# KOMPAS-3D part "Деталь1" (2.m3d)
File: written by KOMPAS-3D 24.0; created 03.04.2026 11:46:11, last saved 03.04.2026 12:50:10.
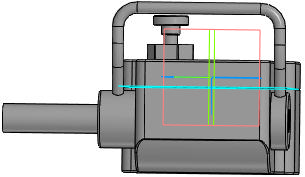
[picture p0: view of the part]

Document properties: Автор: R2D2; Полное имя файла: E:\Работа\Зайцев\Аксессуары для пневмоприводов\Ручной дублер DN.ru\MON1-250-T26-ISO Ручной дублер DN.ru\исходные материалы\2.m3d

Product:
- Body: Тело 2  | qty 1
    Масса: 4.429213
- Part/product: Деталь1
    Масса: 5.630796
    additional columns: Типовые

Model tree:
1. Операция без истории:1
2. Элемент выдавливания:1  (with: Грань.Операция без истории:1)
     Расстояние 1 = 0.5
3. Эскиз:1  (with: Ребро.Операция без истории:1)
4. Элемент выдавливания:2
     Расстояние 1 = 105; Расстояние 2 = 45
5. Эскиз:2  (with: Грань.Операция без истории:1)
6. Элемент выдавливания:3  (with: Грань.Операция без истории:1)
     Расстояние 2 = 19
7. Эскиз:3  (with: Ребро.Операция без истории:1)
8. Элемент выдавливания:4
     Расстояние 1 = 500
9. Смещенная плоскость:1  (with: Грань.Операция без истории:1)
     Расстояние = 14
10. Эскиз:4  (with: Ребро.Операция без истории:1, Вершина.Операция без истории:1)
11. Элемент выдавливания:5
     Расстояние 2 = 0.5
